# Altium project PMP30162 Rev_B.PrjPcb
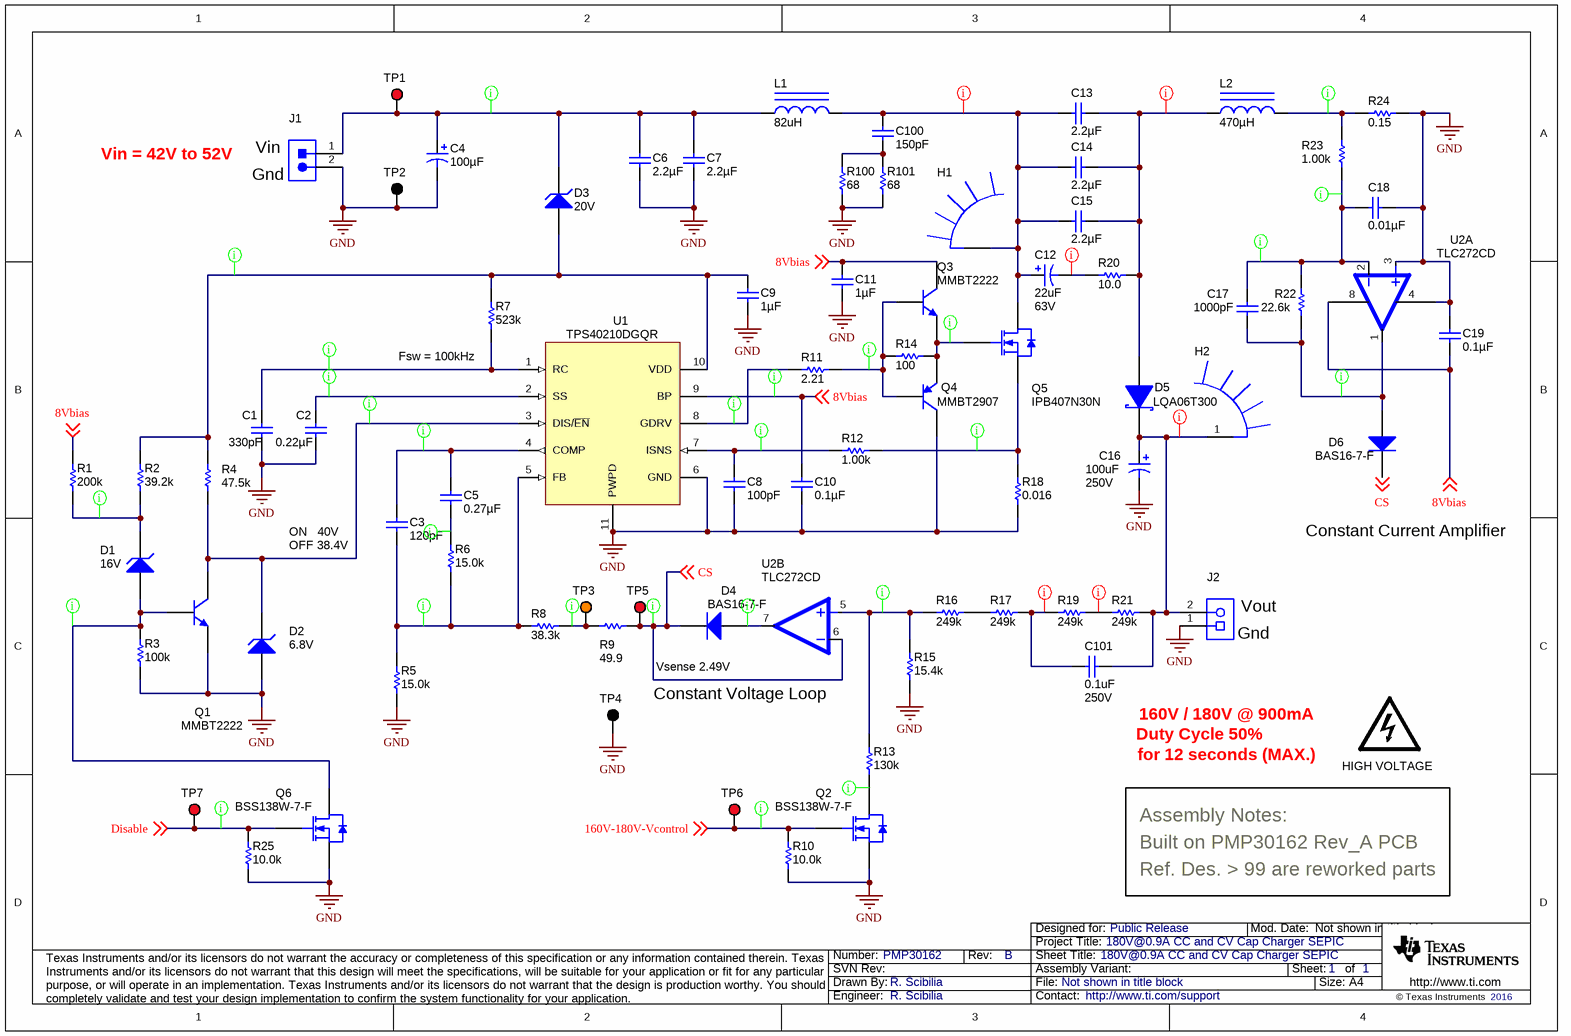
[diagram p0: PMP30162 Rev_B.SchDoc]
CopyrightYear: 2016; PRJ_Customer: Public Release; PRJ_Engineer: R. Scibilia; PRJ_Number: PMP30162; PRJ_Title: 180V@0.9A CC and CV Cap Charger SEPIC; SCH_Rev: B; TechSupport: http://www.ti.com/support
1 sheet, 76 parts. Net scope: global (net labels, ports and power ports of the same name join across sheets).
Board file: PMP30162 Rev_A PCB.PcbDoc

## Sheet PMP30162 Rev_B.SchDoc: 180V@0.9A CC and CV Cap Charger SEPIC
size A4; Date: Not shown in title block; ApprovedBy: Not shown in title block; CheckedBy: Not shown in title block; Author: Not shown in title block; CompanyName: Not shown in title block; DrawnBy: R. Scibilia; Engineer: Not shown in title block; Organization: Not shown in title block; Address1: Not shown in title block; Address2: Not shown in title block; Address3: Not shown in title block; Address4: Not shown in title block; DocumentNumber: 1; Revision: Use project parameter SCH_Rev; SheetNumber: 1; SheetTotal: 1; PageSetup: Record=PageOptions¦CenterHorizontal=True¦CenterVertical=True¦PrintScale=0.70¦XCorrection=1.00¦YCorrection=1.00¦PrintKind=0¦BorderSize=5000000¦LeftOffset=0¦BottomOffset=0¦Orientation=2¦PaperLength=1000¦PaperWidth=1000¦Scale=100¦PaperSource=15¦PrintQuality=600¦MediaType=1¦DitherType=10¦PaperKind=A4¦PrintScaleMode=1

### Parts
C1  ValueDisplayed: 330pF  [0603]  (hidden comment: GRM188R71H331KA01D)
C2  ValueDisplayed: 0.22µF  [0603]  (hidden comment: GRM188R71E224KA88D)
C3  ValueDisplayed: 120pF  [0603]  (hidden comment: C0603C121J5GACTU)
C4  ValueDisplayed: 100µF  [CAPSMT_62_KE0]  (hidden comment: EMVY800ATR101MKE0S)
C5  ValueDisplayed: 0.27µF  [0603]  (hidden comment: GRM188R71C274KA01D)
C6  ValueDisplayed: 2.2µF  [1210_210]  (hidden comment: C1210C225K1RACTU)
C7  ValueDisplayed: 2.2µF  [1210_210]  (hidden comment: C1210C225K1RACTU)
C8  ValueDisplayed: 100pF  [0603]  (hidden comment: 06033C101KAT2A)
C9  ValueDisplayed: 1µF  [0805_HV]  (hidden comment: GRM21BR71H105KA12L)
C10  ValueDisplayed: 0.1µF  [0603]  (hidden comment: GCM188R71H104KA57D)
C11  ValueDisplayed: 1µF  [0805_HV]  (hidden comment: GRM21BR71H105KA12L)
C12  value 22uF  Value2: 63V  [SM_RADIAL_D8]  (hidden comment: EEE-FK1J220XP)
C13  ValueDisplayed: 2.2µF  [1210_210]  (hidden comment: C1210C225K1RACTU)
C14  ValueDisplayed: 2.2µF  [1210_210]  (hidden comment: C1210C225K1RACTU)
C15  ValueDisplayed: 2.2µF  [1210_210]  (hidden comment: C1210C225K1RACTU)
C16  value 100uF  Value2: 250V  [CAPPR7.5-18X25]  (hidden comment: EEUED2E101S)
C17  ValueDisplayed: 1000pF  [0603]  (hidden comment: GRM188R71H102KA01D)
C18  ValueDisplayed: 0.01µF  [0603]  (hidden comment: GRM188R71H103KA01D)
C19  ValueDisplayed: 0.1µF  [0603]  (hidden comment: GCM188R71H104KA57D)
C100  ValueDisplayed: 150pF  [1206]  (hidden comment: GRM31A5C2J151JW01D)
C101  value 0.1uF  Value2: 250V  [0805_HV]  (hidden comment: C2012X7T2E104K125AA)
D1  value 16V  [SOD-323]  (hidden comment: MMSZ5246BS-7-F)
D2  value 6.8V  [sod-323]  (hidden comment: MMSZ5235BS-7-F)
D3  value 20V  [SOD-123]  (hidden comment: MMSZ5250B-7-F)
D4  BAS16-7-F  [SOT-23]
D5  LQA06T300  [TO-220AC]
D6  BAS16-7-F  [SOT-23]
H1  7109DG  [Aavid_7109DG]  (value not drawn)
H2  274-2AB  [HEATSINK_274-2AB]  (value not drawn)
HIGH_VOLTAGE  DANGER HIGH VOLTAGE  [IEC_HighVoltage_Large]  (value not drawn)  (no BOM)
J1  ED555/2DS  [TERM_BLK_ED555-2DS]  (value not drawn)
J2  691 101 710 002  [Wurth_691101710002]  (value not drawn)
L1  value 82uH  [WE-HCI_2212]  (hidden comment: 74435588200)
L2  ValueDisplayed: 470µH  [WE-PD_1210]  (hidden comment: 7447709471)
Q1  value MMBT2222  [SOT-23]  (hidden comment: MMBT2222ALT1G)
Q2  BSS138W-7-F  [SOT-323]
Q3  value MMBT2222  [SOT-23]  (hidden comment: MMBT2222ALT1G)
Q4  value MMBT2907  [SOT-23]  (hidden comment: MMBT2907ALT1G)
Q5  IPB407N30N  [DDPAK]
Q6  BSS138W-7-F  [SOT-323]
R1  ValueDisplayed: 200k  [0603]  (hidden comment: RC0603FR-07200KL)
R2  ValueDisplayed: 39.2k  [0603]  (hidden comment: RC0603FR-0739K2L)
R3  value 100k  [0603]  (hidden comment: CRCW0603100KFKEA)
R4  ValueDisplayed: 47.5k  [0603]  (hidden comment: RC0603FR-0747K5L)
R5  ValueDisplayed: 15.0k  [0603]  (hidden comment: RC0603FR-0715KL)
R6  ValueDisplayed: 15.0k  [0603]  (hidden comment: RC0603FR-0715KL)
R7  ValueDisplayed: 523k  [0603]  (hidden comment: RC0603FR-07523KL)
R8  ValueDisplayed: 38.3k  [0603]  (hidden comment: RC0603FR-0738K3L)
R9  value 49.9  [0603]  (hidden comment: CRCW060349R9FKEA)
R10  value 10.0k  [0603]  (hidden comment: CRCW060310K0FKEA)
R11  ValueDisplayed: 2.21  [0603]  (hidden comment: RC0603FR-072R21L)
R12  value 1.00k  [0603]  (hidden comment: CRCW06031K00FKEA)
R13  ValueDisplayed: 130k  [0603]  (hidden comment: RC0603FR-07130KL)
R14  ValueDisplayed: 100  [0603]  (hidden comment: RC0603FR-07100RL)
R15  ValueDisplayed: 15.4k  [0603]  (hidden comment: RC0603FR-0715K4L)
R16  ValueDisplayed: 249k  [1206]  (hidden comment: ERJ-8ENF2493V)
R17  ValueDisplayed: 249k  [1206]  (hidden comment: ERJ-8ENF2493V)
R18  ValueDisplayed: 0.016  [2512]  (hidden comment: ERJ-M1WSF16MU)
R19  ValueDisplayed: 249k  [1206]  (hidden comment: ERJ-8ENF2493V)
R20  ValueDisplayed: 10.0  [2010]  (hidden comment: CRCW201010R0FKEF)
R21  ValueDisplayed: 249k  [1206]  (hidden comment: ERJ-8ENF2493V)
R22  ValueDisplayed: 22.6k  [0603]  (hidden comment: RC0603FR-0722K6L)
R23  ValueDisplayed: 1.00k  [0603]  (hidden comment: CRCW06031K00FKEA)
R24  ValueDisplayed: 0.15  [2010]  (hidden comment: CSR2010FTR150)
R25  value 10.0k  [0603]  (hidden comment: CRCW060310K0FKEA)
R100  ValueDisplayed: 68  [2010]  (hidden comment: CRCW201068R0JNEF)
R101  ValueDisplayed: 68  [2010]  (hidden comment: CRCW201068R0JNEF)
TP1  5000  [Keystone5000]  (value not drawn)
TP2  5001  [Keystone5001]  (value not drawn)
TP3  5003  [Keystone5003]  (value not drawn)
TP4  5001  [Keystone5001]  (value not drawn)
TP5  5000  [Keystone5000]  (value not drawn)
TP6  5000  [Keystone5000]  (value not drawn)
TP7  5000  [Keystone5000]  (value not drawn)
U1  TPS40210DGQR  [DGQ0010D_N]
U2  TLC272CD  [D0008A_N]  (parts A,B of 2)

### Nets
GND: C1.2 C2.2 C4.2(-) C6.2 C7.2 C8.2 C9.2 C10.2 C11.2 C16.2(-) C18.1 C19.1 D2.2(A) J1.2 J2.1 Q1.2(E) Q2.2(S) Q4.3(C) Q6.2(S) R3.1 R5.1 R10.2 R15.1 R18.1 R24.2 R25.2 R100.1 R101.1 TP2.1 TP4.1 U1.6(GND) U1.11(PWPD) U2.3(IN+) U2.4(GND)
8Vbias: C10.1 C11.1 C19.2 Q3.3(C) R1.2 U1.9(BP) U2.8(VCC) ; off-sheet 8Vbias
160V-180V-Vcontrol: Q2.1(G) R10.1 TP6.1 ; off-sheet 160V-180V-Vcontrol
CS: D4.3(K) D6.3(K) R9.2 TP5.1 U2.6(IN-) ; off-sheet CS
Disable: Q6.1(G) R25.1 TP7.1 ; off-sheet Disable
NetC1_1: C1.1 R7.1 U1.1(RC)
NetC2_1: C2.1 U1.2(SS)
NetC3_1: C3.1 C5.1 U1.4(COMP)
NetC3_2: C3.2 R5.2 R6.1 R8.1 U1.5(FB)
NetC4_1: C4.1(+) C6.1 C7.1 D3.1(K) J1.1 L1.1 TP1.1
NetC5_2: C5.2 R6.2
NetC8_1: C8.1 R12.1 U1.7(ISNS)
NetC9_1: C9.1 D3.2(A) R2.2 R4.2 R7.2 U1.10(VDD)
NetC12_1: C12.1(+) C13.2 C14.2 C15.2 C100.1 H1.1 L1.2 Q5.4(D)
NetC12_2: C12.2(-) R20.1
NetC13_1: C13.1 C14.1 C15.1 D5.3(K) L2.1 R20.2
NetC16_1: C16.1(+) C101.1 D5.1(A) H2.1 J2.2 R21.1
NetC17_1: C17.1 C18.2 R22.2 R23.2 U2.2(IN-)
NetC17_2: C17.2 D6.1(A) R22.1 U2.1(OUT1)
NetC100_2: C100.2 R100.2 R101.2
NetC101_2: C101.2 R17.1 R19.2
NetD1_1: D1.1(K) R1.1 R2.1
NetD1_2: D1.2(A) Q1.1(B) Q6.3(D) R3.2
NetD2_1: D2.1(K) Q1.3(C) R4.1 U1.3(DIS/~{EN})
NetD4_1: D4.1(A) U2.7(OUT)
NetL2_2: L2.2 R23.1 R24.1
NetQ2_3: Q2.3(D) R13.1
NetQ3_1: Q3.1(B) Q4.1(B) R11.2 R14.1
NetQ3_2: Q3.2(E) Q4.2(E) Q5.1(G) R14.2
NetQ5_3: Q5.3(S) R12.2 R18.2
NetR8_2: R8.2 R9.1 TP3.1
NetR11_1: R11.1 U1.8(GDRV)
NetR13_2: R13.2 R15.2 R16.2 U2.5(IN+)
NetR16_1: R16.1 R17.2
NetR19_1: R19.1 R21.2

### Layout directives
rule Clearance Constraint [Clearance = 20mil]: NetC12_1, NetC12_2, NetC13_1, NetC16_1, NetC101_2, NetR19_1
rule Clearance Constraint [Clearance = 10mil]: 8Vbias, 160V-180V-Vcontrol, CS, Disable, NetC1_1, NetC2_1, NetC3_1, NetC3_2, NetC4_1, NetC5_2, NetC8_1, NetC9_1, NetC17_1, NetC17_2, NetD1_1, NetD1_2, NetD2_1, NetD4_1, NetL2_2, NetQ2_3, NetQ3_1, NetQ3_2, NetQ5_3, NetR8_2, NetR11_1, NetR13_2

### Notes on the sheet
- Vin = 42V to 52V
- (near J1) Vin
- (near J1) Gnd
- (near R7) Fsw = 100kHz
- ON   40V
- (near C3) OFF 38.4V
- Constant Current Amplifier
- (near J2) Vout
- (near J2) Gnd
- Constant Voltage Loop
- Vsense 2.49V
- 160V / 180V @ 900mA
- Duty Cycle 50%
- for 12 seconds (MAX.)
- Assembly Notes:
- Built on PMP30162 Rev_A PCB
- Ref. Des. > 99 are reworked parts

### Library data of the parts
C1 = GRM188R71H331KA01D: CAP, CERM, 330pF, 50V, +/-10%, X7R, 0603; Manufacturer: MuRata; Polarized: N; CompType: Capacitor; U/M: EA; Cap_F: 0.00000000033; Tolerance_%: 10; Value1: Unknown; VDC_V: 50; TaMin_C: -55; TaMax_C: 125
C2 = GRM188R71E224KA88D: CAP, CERM, 0.22uF, 25V, +/-10%, X7R, 0603; Manufacturer: MuRata; Polarized: N; CompType: Capacitor; U/M: EA; Cap_F: 0.00000022; Tolerance_%: 10; Value1: Unknown; VDC_V: 25; TaMin_C: -55; TaMax_C: 125
C3 = C0603C121J5GACTU: CAP, CERM, 120 pF, 50 V, +/- 5%, C0G/NP0, 0603; Manufacturer: Kemet; Polarized: N; CompType: Capacitor; Value: 120pF; U/M: EA; Cap_F: 0.00000000012; Tolerance_%: 5; Value1: Unknown; VDC_V: 50; Value2: 50V; TaMin_C: -55; TaMax_C: 125; SizeArea_mm2: 1.28; SizeAreaWB_mm2: 4.68; SizeX_mm: 1.6; SizeY_mm: 0.8; SizeZ_mm: 1; AEC Category: Q200
C4 = EMVY800ATR101MKE0S: CAP, AL, 100 µF, 80 V, +/- 20%, 0.33 ohm, SMD; Manufacturer: Chemi-Con; Polarized: Y; CompType: Capacitor; Value: 100uF; U/M: EA; Cap_F: 0.0001; Tolerance_%: 20; VDC_V: 80; Value2: 80V; ESR_ohm: 0.33; IRMS_A: 0.45; TaMin_C: -40; TaMax_C: 105; Cap_Case: KE0; SizeAreaWB_mm2: 225; SizeArea_mm2: 169; SizeX_mm: 13; SizeZ_mm: 13.5; AEC Category: Q200
C5 = GRM188R71C274KA01D: CAP, CERM, 0.27 µF, 16 V, +/- 10%, X7R, 0603; Manufacturer: MuRata; Polarized: N; CompType: Capacitor; Value: 0.27uF; U/M: EA; Cap_F: 0.00000027; Tolerance_%: 10; Value1: Unknown; VDC_V: 16; Value2: 16V; TaMin_C: -55; TaMax_C: 125; SizeArea_mm2: 1.28; SizeAreaWB_mm2: 4.68; SizeX_mm: 1.6; SizeY_mm: 0.8; SizeZ_mm: 1; AEC Category: Q200
C6 C7 C13-C15 = C1210C225K1RACTU: CAP, CERM, 2.2 µF, 100 V, +/- 10%, X7R, 1210; Manufacturer: Kemet; Polarized: N; CompType: Capacitor; Value: 2.2uF; U/M: EA; Cap_F: 0.0000022; Tolerance_%: 10; Value1: Unknown; VDC_V: 100; Value2: 100V; TaMin_C: -55; TaMax_C: 125; Cap_Case: 1210; SizeArea_mm2: 8; SizeAreaWB_mm2: 14.7; SizeX_mm: 3.2; SizeY_mm: 2.5; SizeZ_mm: 2.1; AEC Category: Q200
C8 = 06033C101KAT2A: CAP, CERM, 100pF, 25V, +/-10%, X7R, 0603; Manufacturer: AVX; Polarized: N; CompType: Capacitor; U/M: EA; Cap_F: 0.0000000001; Tolerance_%: 10; Value1: Unknown; VDC_V: 25; TaMin_C: -55; TaMax_C: 125
C9 C11 = GRM21BR71H105KA12L: CAP, CERM, 1uF, 50V, +/-10%, X7R, 0805; Manufacturer: MuRata; Polarized: N; CompType: Capacitor; U/M: EA; Cap_F: 0.000001; Tolerance_%: 10; Value1: Unknown; VDC_V: 50; TaMin_C: -55; TaMax_C: 125; Cap_Case: 0805
C10 C19 = GCM188R71H104KA57D: CAP, CERM, 0.1uF, 50V, +/-10%, X7R, 0603; Manufacturer: MuRata; Polarized: N; CompType: Capacitor; U/M: EA; Cap_F: 0.0000001; Tolerance_%: 10; ESR_Ohm: 0.02; Value1: 0.02 ohm; VDC_V: 50; IRMS_A: 1.84; TaMin_C: -55; TaMax_C: 125
C12 = EEE-FK1J220XP: CAP, AL, 22 µF, 63 V, +/- 20%, 1.2 ohm, AEC-Q200 Grade 2, SMD; Manufacturer: Panasonic; Polarized: Y; CompType: Capacitor; ValueDisplayed: 22µF; U/M: EA; Cap_F: 0.000022; Tolerance_%: 20; Value1: 1.2 ohm; VDC_V: 63; ESR_ohm: 1.2; IRMS_A: 0.12; TaMin_C: -55; TaMax_C: 105; Cap_Case: D8; SizeAreaWB_mm2: 84.28; SizeArea_mm2: 51.48; SizeX_mm: 7.8; SizeY_mm: 6.6; SizeZ_mm: 7.7; AEC Category: Q200; AEC Grade: 2
C16 = EEUED2E101S: CAP, AL, 100 µF, 250 V, +/- 20%, 0.243706 ohm, TH; Manufacturer: Panasonic; Polarized: Y; CompType: Capacitor; ValueDisplayed: 100µF; U/M: EA; Cap_F: 0.0001; Tolerance_%: 20; VDC_V: 250; IRMS_A: 1.5; TaMin_C: -25; TaMax_C: 105; SizeAreaWB_mm2: 400; SizeArea_mm2: 324; SizeX_mm: 18; SizeZ_mm: 25; AC_Derating: 0.35; AEC Category: Q200
C17 = GRM188R71H102KA01D: CAP, CERM, 1000pF, 50V, +/-10%, X7R, 0603; Manufacturer: MuRata; Polarized: N; CompType: Capacitor; U/M: EA; Cap_F: 0.000000001; Tolerance_%: 10; Value1: Unknown; VDC_V: 50; TaMin_C: -55; TaMax_C: 125
C18 = GRM188R71H103KA01D: CAP, CERM, 0.01uF, 50V, +/-10%, X7R, 0603; Manufacturer: MuRata; Polarized: N; CompType: Capacitor; U/M: EA; Cap_F: 0.00000001; Tolerance_%: 10; Value1: Unknown; VDC_V: 50; TaMin_C: -55; TaMax_C: 125
C100 = GRM31A5C2J151JW01D: CAP, CERM, 150 pF, 630 V, +/- 5%, C0G/NP0, 1206; Manufacturer: MuRata; Polarized: N; CompType: Capacitor; Value: 150pF; U/M: EA; Cap_F: 0.00000000015; Tolerance_%: 5; Value1: Unknown; VDC_V: 630; Value2: 630V; TaMin_C: -55; TaMax_C: 125; SizeArea_mm2: 5.12; SizeAreaWB_mm2: 10.92; SizeX_mm: 3.2; SizeY_mm: 1.6; SizeZ_mm: 1.35; AEC Category: Q200
C101 = C2012X7T2E104K125AA: CAP, CERM, 0.1 µF, 250 V, +/- 10%, X7T, 0805; Manufacturer: TDK; Polarized: N; CompType: Capacitor; ValueDisplayed: 0.1µF; U/M: EA; Cap_F: 0.0000001; Tolerance_%: 10; Value1: Unknown; VDC_V: 250; TaMin_C: -55; TaMax_C: 125; Cap_Case: 0805; SizeArea_mm2: 2.5; SizeAreaWB_mm2: 6.75; SizeX_mm: 2; SizeY_mm: 1.25; SizeZ_mm: 1.45; AEC Category: Q200
D1 = MMSZ5246BS-7-F: Diode, Zener, 16 V, 200 mW, SOD-323; Manufacturer: Diodes Inc.; SymbolCreator: a0412235; U/M: EA; Power_W: 0.2; Vz_V: 16; Value1: 0.2W; RJA_CperW: 350; SizeAreaWB_mm2: 8.695; SizeArea_mm2: 3.645; SizeX_mm: 2.7; SizeY_mm: 1.35; SizeZ_mm: 1; AEC Category: Q101
D2 = MMSZ5235BS-7-F: Diode, Zener, 6.8V, 200mW, SOD-323; Manufacturer: Diodes Inc.; SymbolCreator: a0412235; U/M: EA; Power_W: 0.2; Vz_V: 6.8; Value1: 0.2W; RJA_CperW: 350
D3 = MMSZ5250B-7-F: Diode, Zener, 20 V, 500 mW, SOD-123; Manufacturer: Diodes Inc.; SymbolCreator: a0412235; U/M: EA; Power_W: 0.5; Vz_V: 20; Value1: 0.5W; RJA_CperW: 350; SizeAreaWB_mm2: 13.095; SizeArea_mm2: 6.545; SizeX_mm: 3.85; SizeY_mm: 1.7; SizeZ_mm: 1.35; AEC Category: Q101
D4 D6 = BAS16-7-F: Diode, Ultrafast, 75V, 0.3A, SOT-23; Manufacturer: Diodes Inc.; U/M: EA; Vf_V: 1.125; Value2: 1.125V; Io_A: 0.3; Vr_V: 75
D5 = LQA06T300: Diode, Schottky, 300 V, 6 A, TH; Manufacturer: Power Integrations; SymbolCreator: a0412235; U/M: EA; Vf_V: 1.9; Value1: 6A; Value2: 1.9V; Io_A: 6; Vr_V: 300; TJmax_C: 150; SizeAreaWB_mm2: 397.048; SizeArea_mm2: 312.208; SizeX_mm: 30.02; SizeY_mm: 10.4; SizeZ_mm: 4.82; AEC Category: Q101
H1 = 7109DG: Surface mount heat sink for D2PAK; Manufacturer: Aavid; SymbolCreator: a0412235
H2 = 274-2AB: Heat Sink, TO-220, TH; Manufacturer: Wakefield Solutions; SymbolCreator: a0412235
HIGH_VOLTAGE = IEC_HighVoltage: IEC 61010-1 High Voltage Warning; SymbolCreator: a0412235
J1 = ED555/2DS: Terminal Block, 6A, 3.5mm Pitch, 2-Pos, TH; Manufacturer: On-Shore Technology; SymbolCreator: a0412235; CompType: Connector; U/M: EA
J2 = 691 101 710 002: Terminal Block, 5 mm, 2x1, Tin, TH; Manufacturer: Wurth Elektronik; SymbolCreator: a0412235
L1 = 74435580680: Inductor, Wirewound, Metal Composite, 82 µH, 8.5 A, 0.03 ohm, SMD; Manufacturer: Wurth Elektronik; ValueDisplayed: 82µH; Ind_H: 82E-6; Imax_A: 8.5; Irms: 7A @ 50C rise; Isat: 8.5A @ 30% inductance drop; DCR_ohm: 0.0021; Value2: 8.5A; SizeAreaWB_mm2: 588; SizeArea_mm2: 495; SizeX_mm: 22.5; SizeY_mm: 22; SizeZ_mm: 12.4; AEC Category: Q200
L2 = 7447709471: Inductor, Shielded Drum Core, Ferrite, 470 µH, 1.4 A, 0.56 ohm, SMD; Manufacturer: Wurth Elektronik; Value: 470uH; Ind_H: 470.0E-6; Imax_A: 1.4; Irms: 1.4A @ 40C rise; Isat: 1.5A @ 10% inductance drop; DCR_ohm: 0.56; Value2: 1.4A; SizeAreaWB_mm2: 196; SizeArea_mm2: 144; SizeX_mm: 12; SizeZ_mm: 10; AEC Category: Q200
Q1 Q3 = MMBT2222ALT1G, ON Semiconductor: Transistor, NPN, 40 V, 0.6 A, SOT-23; CompType: BJT; PNP: 0; NPN: 1; Vceo_V: 40; IcRated_A: 0.6; Value1: 0.6 A; TaMin_C: -55; TaMax_C: 150; U/M: EA; AEC Category: Q101
Q2 Q6 = BSS138W-7-F: MOSFET, N-CH, 50 V, 0.2 A, SOT-323; Manufacturer: Diodes Inc.; Alternate Manufacturer: None; U/M: EA; ChType: N; VdsMax_V: 50; Value1: 3.5 ohm; Rdson45_ohm: 3.5; Value2: ? nC; Vgs_V: 1.5; IdsMax_A: 0.2; SizeAreaWB_mm2: 10.24; SizeArea_mm2: 4.84; SizeX_mm: 2.2; SizeZ_mm: 1.1; AEC Category: Q101
Q4 = MMBT2907ALT1G, ON Semiconductor: Transistor, PNP, 60 V, 0.6 A, SOT-23; CompType: BJT; PNP: 1; NPN: 0; Vceo_V: 60; Vcesat1_V: 1.6; IcRated_A: 0.6; Value1: 0.6 A; TaMin_C: -55; TaMax_C: 150; U/M: EA; AEC Category: Q101
Q5 = IPB60R190C6: MOSFET, N-CH, 300 V, 44 A, DDPAK; Manufacturer: Infineon Technologies; Alternate Manufacturer: None; U/M: EA; ChType: N; VdsMax_V: 300; Value1: 0.04 ohm; Rdson45_ohm: 0.19; Value2: 65 nC; QgTyp_nC: 63; Vgs_V: 3.5; IdsMax_A: 20.2; SizeAreaWB_mm2: 209.6992; SizeArea_mm2: 154.8892; SizeX_mm: 15.245; SizeY_mm: 10.16; SizeZ_mm: 4.445; AEC Category: Q101
R1 = RC0603FR-07200KL: RES, 200 k, 1%, 0.1 W, 0603; Manufacturer: Yageo America; CompType: Resistor; Value: 200k; Res_ohm: 200000; Tolerance_%: 1; Power_W: 0.1; Value2: 0.1W; VDC_V: 150; TempCo: 200 ppm/C; SizeArea_mm2: 1.28; SizeX_mm: 1.6; SizeY_mm: 0.8; EIA_Code: E96; U/M: EA; AEC Category: Q200
R2 = RC0603FR-0739K2L: RES, 39.2 k, 1%, 0.1 W, 0603; Manufacturer: Yageo America; CompType: Resistor; Value: 39.2k; Res_ohm: 39200; Value_Code: 39k2; Tolerance_%: 1; Power_W: 0.1; Value2: 0.1W; VDC_V: 150; TempCo: 200 ppm/C; SizeArea_mm2: 1.28; SizeX_mm: 1.6; SizeY_mm: 0.8; EIA_Code: E96; U/M: EA; AEC Category: Q200
R3 = CRCW0603100KFKEA: RES, 100k ohm, 1%, 0.1W, 0603; Manufacturer: Vishay-Dale; CompType: Resistor; Res_ohm: 100000; Tolerance_%: 1; Power_W: 0.1; VDC_V: 75; TempCo: 100 ppm/C; EIA_Code: E96; U/M: EA
R4 = RC0603FR-0747K5L: RES, 47.5 k, 1%, 0.1 W, 0603; Manufacturer: Yageo America; CompType: Resistor; Value: 47.5k; Res_ohm: 47500; Value_Code: 47k5; Tolerance_%: 1; Power_W: 0.1; Value2: 0.1W; VDC_V: 150; TempCo: 200 ppm/C; SizeArea_mm2: 1.28; SizeX_mm: 1.6; SizeY_mm: 0.8; EIA_Code: E96; U/M: EA; AEC Category: Q200
R5 R6 = RC0603FR-0715KL: RES, 15.0 k, 1%, 0.1 W, 0603; Manufacturer: Yageo America; CompType: Resistor; Value: 15.0k; Res_ohm: 15000; Value_Code: 15k0; Tolerance_%: 1; Power_W: 0.1; Value2: 0.1W; VDC_V: 150; TempCo: 200 ppm/C; SizeArea_mm2: 1.28; SizeX_mm: 1.6; SizeY_mm: 0.8; EIA_Code: E96; U/M: EA; AEC Category: Q200
R7 = RC0603FR-07523KL: RES, 523 k, 1%, 0.1 W, 0603; Manufacturer: Yageo America; CompType: Resistor; Value: 523k; Res_ohm: 523000; Tolerance_%: 1; Power_W: 0.1; Value2: 0.1W; VDC_V: 150; TempCo: 200 ppm/C; SizeArea_mm2: 1.28; SizeX_mm: 1.6; SizeY_mm: 0.8; EIA_Code: E96; U/M: EA; AEC Category: Q200
R8 = RC0603FR-0738K3L: RES, 38.3 k, 1%, 0.1 W, 0603; Manufacturer: Yageo America; CompType: Resistor; Value: 38.3k; Res_ohm: 38300; Value_Code: 38k3; Tolerance_%: 1; Power_W: 0.1; Value2: 0.1W; VDC_V: 150; TempCo: 200 ppm/C; SizeArea_mm2: 1.28; SizeX_mm: 1.6; SizeY_mm: 0.8; EIA_Code: E96; U/M: EA; AEC Category: Q200
R9 = CRCW060349R9FKEA: RES, 49.9 ohm, 1%, 0.1W, 0603; Manufacturer: Vishay-Dale; CompType: Resistor; Value_Code: 49R9; Tolerance_%: 1; Power_W: 0.1; VDC_V: 75; TempCo: 100 ppm/C; EIA_Code: E96; U/M: EA
R10 R25 = CRCW060310K0FKEA: RES, 10.0k ohm, 1%, 0.1W, 0603; Manufacturer: Vishay-Dale; CompType: Resistor; Res_ohm: 10000; Value_Code: 10k0; Tolerance_%: 1; Power_W: 0.1; VDC_V: 75; TempCo: 100 ppm/C; EIA_Code: E96; U/M: EA
R11 = RC0603FR-072R21L: RES, 2.21, 1%, 0.1 W, 0603; Manufacturer: Yageo America; CompType: Resistor; Value: 2.21; Value_Code: 2R21; Tolerance_%: 1; Power_W: 0.1; Value2: 0.1W; VDC_V: 150; TempCo: 200 ppm/C; SizeArea_mm2: 1.28; SizeX_mm: 1.6; SizeY_mm: 0.8; EIA_Code: E96; U/M: EA; AEC Category: Q200
R12 = CRCW06031K00FKEA: RES, 1.00k ohm, 1%, 0.1W, 0603; Manufacturer: Vishay-Dale; CompType: Resistor; Res_ohm: 1000; Value_Code: 1k00; Tolerance_%: 1; Power_W: 0.1; VDC_V: 75; TempCo: 100 ppm/C; EIA_Code: E96; U/M: EA
R13 = RC0603FR-07130KL: RES, 130 k, 1%, 0.1 W, 0603; Manufacturer: Yageo America; CompType: Resistor; Value: 130k; Res_ohm: 130000; Tolerance_%: 1; Power_W: 0.1; Value2: 0.1W; VDC_V: 150; TempCo: 200 ppm/C; SizeArea_mm2: 1.28; SizeX_mm: 1.6; SizeY_mm: 0.8; EIA_Code: E96; U/M: EA; AEC Category: Q200
R14 = RC0603FR-07100RL: RES, 100, 1%, 0.1 W, 0603; Manufacturer: Yageo America; CompType: Resistor; Value: 100; Value_Code: 100R; Tolerance_%: 1; Power_W: 0.1; Value2: 0.1W; VDC_V: 150; TempCo: 200 ppm/C; SizeArea_mm2: 1.28; SizeX_mm: 1.6; SizeY_mm: 0.8; EIA_Code: E96; U/M: EA; AEC Category: Q200
R15 = RC0603FR-0715K4L: RES, 15.4 k, 1%, 0.1 W, 0603; Manufacturer: Yageo America; CompType: Resistor; Value: 15.4k; Res_ohm: 15400; Value_Code: 15k4; Tolerance_%: 1; Power_W: 0.1; Value2: 0.1W; VDC_V: 150; TempCo: 200 ppm/C; SizeArea_mm2: 1.28; SizeX_mm: 1.6; SizeY_mm: 0.8; EIA_Code: E96; U/M: EA; AEC Category: Q200
R16 R17 R19 R21 = ERJ-8ENF2493V: RES, 249 k, 1%, 0.25 W, 1206; Manufacturer: Panasonic; CompType: Resistor; Value: 249k; Res_ohm: 249000; Tolerance_%: 1; Power_W: 0.25; Value2: 0.25W; VDC_V: 200; TempCo: 100 ppm/C; SizeArea_mm2: 5.12; SizeX_mm: 3.2; SizeY_mm: 1.6; SizeZ_mm: 1.35; EIA_Code: E96; U/M: EA; AEC Category: Q200
R18 = ERJ-M1WSF16MU: RES, 0.016, 1%, 1 W, 2512; Manufacturer: Panasonic; CompType: Resistor; Value: 0.016; Value_Code: R016; Tolerance_%: 1; Value2: 1W; TempCo: 100 ppm/C; SizeArea_mm2: 20.16; SizeX_mm: 6.3; SizeY_mm: 3.2; SizeZ_mm: 0.71; EIA_Code: E96; U/M: EA; AEC Category: Q200
R20 = CRCW201010R0FKEF: RES, 10.0, 1%, 0.75 W, AEC-Q200 Grade 0, 2010; Manufacturer: Vishay-Dale; CompType: Resistor; Value: 10.0; Res_ohm: 10; Value_Code: 10R0; Tolerance_%: 1; Power_W: 0.75; Value2: 0.75W; VDC_V: 400; TempCo: 100 ppm/C; SizeArea_mm2: 12.5; SizeX_mm: 5; SizeY_mm: 2.5; SizeZ_mm: 1.66; EIA_Code: E96; U/M: EA; AEC Category: Q200; AEC Qualified: Y; AEC Grade: 0
R22 = RC0603FR-0722K6L: RES, 22.6 k, 1%, 0.1 W, 0603; Manufacturer: Yageo America; CompType: Resistor; Value: 22.6k; Res_ohm: 22600; Value_Code: 22k6; Tolerance_%: 1; Power_W: 0.1; Value2: 0.1W; VDC_V: 150; TempCo: 200 ppm/C; SizeArea_mm2: 1.28; SizeX_mm: 1.6; SizeY_mm: 0.8; EIA_Code: E96; U/M: EA; AEC Category: Q200
R23 = CRCW06031K00FKEA: RES, 1.00 k, 1%, 0.1 W, 0603; Manufacturer: Vishay-Dale; CompType: Resistor; Value: 1.00k; Res_ohm: 1000; Value_Code: 1k00; Tolerance_%: 1; Power_W: 0.1; Value2: 0.1W; VDC_V: 75; TempCo: 100 ppm/C; EIA_Code: E96; U/M: EA
R24 = CSR2010FTR150: RES, 0.15, 1%, 1 W, 2010; Manufacturer: Stackpole Electronics Inc; CompType: Resistor; Value: 0.15; Value_Code: R150; Tolerance_%: 1; Value2: 1W; TempCo: 100 ppm/C; SizeArea_mm2: 12.5; SizeX_mm: 5; SizeY_mm: 2.5; SizeZ_mm: 1.66; EIA_Code: E96; U/M: EA; AEC Category: Q200
R100 R101 = CRCW201068R0JNEF: RES, 68, 5%, 0.75 W, AEC-Q200 Grade 0, 2010; Manufacturer: Vishay-Dale; CompType: Resistor; Value: 68; Value_Code: 68R0; Tolerance_%: 5; Power_W: 0.75; Value2: 0.75W; VDC_V: 400; TempCo: 200 ppm/C; SizeArea_mm2: 12.5; SizeY_mm: 2.5; SizeZ_mm: 1.66; EIA_Code: E24; U/M: EA; AEC Category: Q200; AEC Qualified: Y; AEC Grade: 0
TP1 TP5-TP7 = 5000: Test Point, Miniature, Red, TH; Manufacturer: Keystone; CompType: Test Point Loop; U/M: EA
TP2 TP4 = 5001: Test Point, Miniature, Black, TH; Manufacturer: Keystone; CompType: Test Point Loop; U/M: EA
TP3 = 5003: Test Point, Miniature, Orange, TH; Manufacturer: Keystone; CompType: Test Point Loop; U/M: EA
U1 = TPS40210DGQR: 4.5-V TO 52-V INPUT CURRENT MODE BOOST CONTROLLER, DGQ0010D; Alternate Manufacturer: Texas Instruments; SymbolCreator: a0412235; CompType: IC; U/M: EA
U2 = TLC272CD: IC, Precision Dual Operational Amplifiers; Manufacturer: Texas Instruments; Alternate Manufacturer: None; Area: 75900

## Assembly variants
001: all parts fitted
